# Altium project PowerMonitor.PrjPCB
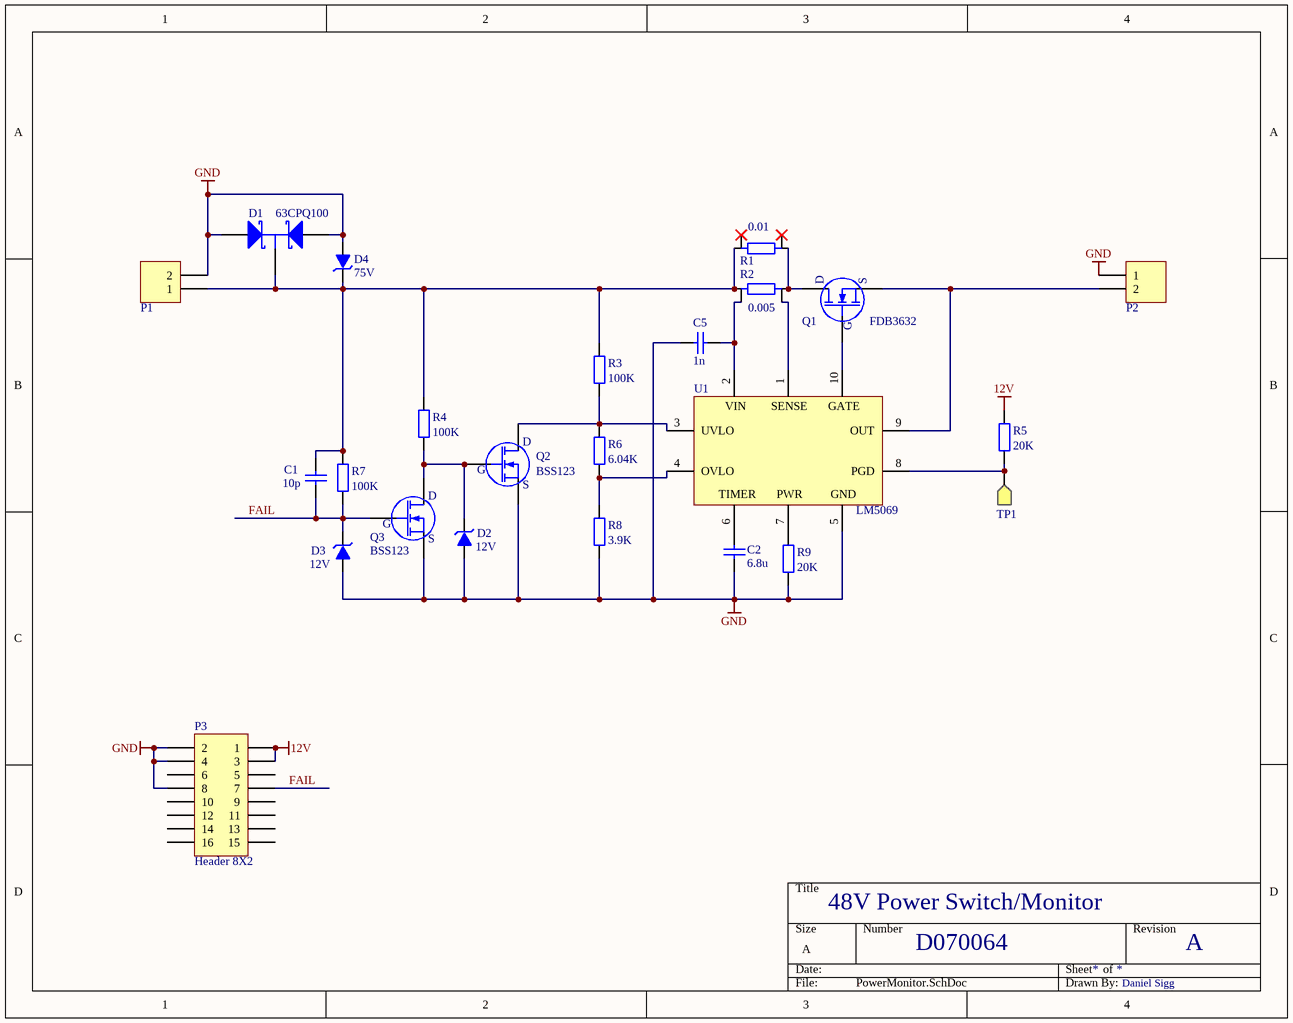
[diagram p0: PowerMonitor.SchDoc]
1 sheet, 24 parts. Net scope: global (net labels, ports and power ports of the same name join across sheets).
Board file: PowerMonitor.PcbDoc

## Sheet PowerMonitor.SchDoc: D070064
size A; Engineer: Daniel Sigg; Revision: A; PageSetup: Record=PageOptions|CenterHorizontal=True|CenterVertical=True|PrintScale=1.12|XCorrection=1.00|YCorrection=1.00|PrintKind=0|BorderSize=5000000|LeftOffset=0|BottomOffset=0|Orientation=2|PaperLength=1000|PaperWidth=1000|Scale=100|PaperSource=7|PrintQuality=-4|MediaType=1|DitherType=10|PaperKind=Letter|PrintScaleMode=1

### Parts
C1  10p  [CC2013-0805]
C2  6.8u  [CC3216-1206]
C5  1n  [CC2013-0805]
D1  63CPQ100  [TO-247AC]
D2  Voltage Rating: 12V  [DO-SOD123]  (hidden comment: zener diode)
D3  Voltage Rating: 12V  [DO-SOD123]  (hidden comment: zener diode)
D4  Voltage Rating: 75V  [DO-41]  (hidden comment: zener diode)
P1  TBlock_10.16_2  [TBLOCK-10.16-2]  (value not drawn)
P2  TBlock_10.16_2  [TBLOCK-10.16-2]  (value not drawn)
P3  Header 8X2  [HDR2X8]
Q1  FDB3632  [D2PAK]
Q2  BSS123  [SO-G3/C2.25]
Q3  BSS123  [SO-G3/C2.25]
R1  0.01  [RW10862-4325]
R2  0.005  [RW10862-4325]
R3  100K  [CR2012-0805]
R4  100K  [CR2012-0805]
R5  20K  [CR2012-0805]
R6  6.04K  [CR2012-0805]
R7  100K  [CR2012-0805]
R8  3.9K  [CR2012-0805]
R9  20K  [CR2012-0805]
TP1  Testpoint  [TP1]  (value not drawn)
U1  LM5069  [TSSO3x5-G10]

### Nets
12V: P3.1 P3.3 R5.2
GND: C2.2 C5.1 D1.1(A1) D1.3(A2) D2.1(A) D3.1(A) D4.1(A) P1.2 P2.1 P3.2 P3.4 P3.8 Q2.2(S) Q3.2(S) R8.1 R9.1 U1.5(GND)
FAIL: C1.1 D3.2(K) P3.7 Q3.1(G) R7.1
NetC1_2: C1.2 D1.2(K) D4.2(K) P1.1 R1.4 R2.1 R3.2 R4.2 R7.2
NetC2_1: C2.1 U1.6(TIMER)
NetC5_2: C5.2 R2.2 U1.2(VIN)
NetD2_2: D2.2(K) Q2.1(G) Q3.3(D) R4.1
NetP2_2: P2.2 Q1.3(S) U1.9(OUT)
NetQ1_1: Q1.1(G) U1.10(GATE)
NetQ1_2: Q1.2(D) R1.1 R2.4
NetQ2_3: Q2.3(D) R3.1 R6.2 U1.3(UVLO)
NetR2_3: R2.3 U1.1(SENSE)
NetR5_1: R5.1 TP1.1 U1.8(PGD)
NetR6_1: R6.1 R8.2 U1.4(OVLO)
NetR9_2: R9.2 U1.7(PWR)

Not connected (* = marked no-connect by the designer): P3 5 6 9 10 11 12 13 14 15 16; R1 2* 3*

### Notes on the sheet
- 48V Power Switch/Monitor
- D070064
- A
- Daniel Sigg

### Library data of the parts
C1 = ChipCap: Capacitor, surface mount; Part Number: 311-1099-1-ND; Tolerance: 10%; Voltage Rating: 100V
C2 = ChipCap: Capacitor, surface mount; Part Number: 399-3025-1-ND; Tolerance: 10%; Voltage Rating: 25V
C5 = ChipCap: Capacitor, surface mount; Part Number: 311-1122-1-ND; Tolerance: 10%; Voltage Rating: 100V
D1 = 30CPQ100: Schottky Rectifier; Part Number: 63CPQ100PBF-ND
D2 D3 = DIODE_ZENER: Single zener diode; Part Number: BZT52C12-FDICT-ND
D4 = DIODE_ZENER: Single zener diode; Part Number: 1N5374BGOS-ND
P1 P2 = TBlock_10.16_2: Terminal block, 10.16mm, 2-Pin; Part Number: WM5964-ND
P3 = Header 8X2: Header, 8-Pin, Dual row; Part Number: A31169-ND
Q1 = MOSFET-N: Power MOSFET, N-channel; Part Number: FDB3632CT-ND
Q2 Q3 = FDV301N: FDV301N, Digital FET, N-channel, SOT23; Part Number: BSS123NCT-ND
R1 = RW1S0CK: Four-Terminal Current Sense Resistor; Part Number: RW1S0CKR010DE-ND; Tolerance: 1%
R2 = RW1S0CK: Four-Terminal Current Sense Resistor; Part Number: RW1S0CKR005DE-ND; Tolerance: 1%
R3 R4 R7 = Res2: Resistor; Part Number: RR12P100KBCT-ND; Tolerance: 0.1%
R5 = Res2: Resistor; Part Number: RR12P33.0KBCT-ND; Tolerance: 0.1%
R6 = Res2: Resistor; Part Number: RR12P6.04KBCT-ND; Tolerance: 0.1%
R8 = Res2: Resistor; Part Number: RR12P3.9KBCT-ND; Tolerance: 0.1%
R9 = Res2: Resistor; Part Number: RR12P20.0KBCT-ND; Tolerance: 0.1%
TP1 = TP_SIGNAL: Testpoint, yellow; Part Number: 5009K-ND
U1 = LM5069: Positive High Voltage Hot Swap / Inrush Current  Controller with Power Limiting; Part Number: LM5069MM-1CT-ND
